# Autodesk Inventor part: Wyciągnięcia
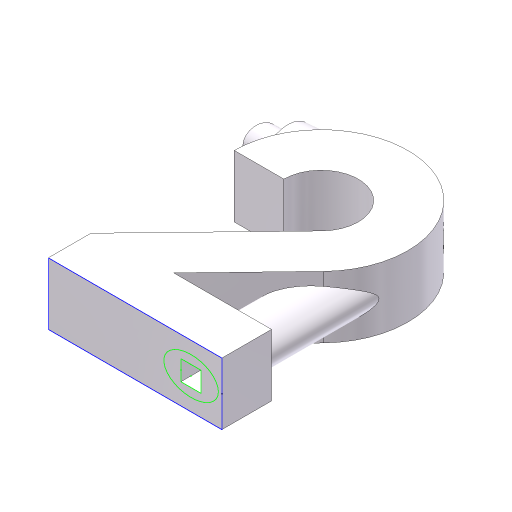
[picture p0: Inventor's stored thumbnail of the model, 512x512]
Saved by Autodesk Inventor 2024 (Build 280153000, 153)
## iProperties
Company: ATC
Created: 2023-03
Part Number: Wyciągnięcia
Document SubType Name: Modeling
Designer: Andrzej Jaskulski
Density: 1 g/cm^3
Material: Kurs-AJ
Appearance: Kurs-AJ
Checked By: A.J.
Engr Approved By: Andrzej Jaskulski
Mfg Approved By: Andrzej Jaskulski
Authority: A.J.
Title: A.J.: Kurs R2024-MEP
Author: Andrzej Jaskulski
Revision Number: 1/24
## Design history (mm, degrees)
sketch "Zarys dwójki"
  geometry: L1 (0, 0)-(140, 0); L2 (140, 0)-(140, 40); L3 (140, 40)-(61.086, 40); L4 (0, 0)-(0, 34.326); L5 (0, 34.326)-(91.58, 129.16); L6 (61.086, 40)-(120.354, 101.374); L7 (40, 150)-(0, 150); A1 r 30 centre (70, 150) between (91.58, 129.16) and (40, 150); A2 r 70 centre (70, 150) between (120.354, 101.374) and (0, 150)
  constraints: 14 end point, 4 point on circle, 3 perpendicular, 2 centre point, 2 parallel, 2 tangent, 1 coincident, 1 horizontal, 1 point on line, 1 other
  dimensions: "d0" = 140 distance of L1.start L1.end; "d1" = 150 distance from line of A1.centre L1; "d2" = 70 radius of A2; "d3" = 30 radius of A1; "d4" = 70 distance from line of L4 A1.centre; "d5" = 46 deg angle of L6 L3; "d6" = 40 distance of L1.end L2.end
extrude "Dwójka" new body sketch "Zarys dwójki" distance "d7" = 50; taper "d8" = 0 deg
node "Odsunięta od Stycznej do Walca"
  node "Styczna do Walca"
node "Oś powierzchni walcowej"
sketch "Okręgi"
  geometry: L1 (0, 150)-(50, 150) reference; C1 r 12 at (25, 193); C2 r 21.5 at (25, 193); 1 further point
  constraints: 2 centre point, 1 coincident, 1 midpoint, 1 vertical alignment
extrude "Wyciągnięcie do Powierzchni 1" join sketch "Okręgi" stored distance "d18" = 10; taper "d19" = 4 deg
extrude "Wyciągnięcie do Płaszczyzny 1" join sketch "Okręgi" stored distance "d20" = 10; taper "d21" = -2 deg
sketch "Elipsa i Kwadrat"
  geometry: L1 (140, 0)-(140, 50) reference; L2 (106.938, 16.938)-(123.062, 16.938); L3 (123.062, 16.938)-(123.062, 33.062); L4 (123.062, 33.062)-(106.938, 33.062); L5 (106.938, 33.062)-(106.938, 16.938); L6 (140, 50)-(0, 50) reference; L7 (0, 0)-(0, 50) reference; L8 (0, 0)-(140, 0) reference; 4 further points; 1 other entity
  constraints: 8 end point, 3 midpoint, 2 horizontal alignment, 2 parallel, 2 perpendicular, 1 horizontal, 1 vertical alignment, 2 other
extrude "Wyciągnięcie Między" join sketch "Elipsa i Kwadrat" stored distance "d24" = 10; taper "d25" = 0 deg
extrude "Wyciągnięcie przelotowe 1" cut sketch "Elipsa i Kwadrat" extent not by distance; stored distance "d26" = 0; taper "d27" = 0 deg
node "Bryła1"
node "Korpusy bryłowe"
node "Korpusy powierzchniowe"
